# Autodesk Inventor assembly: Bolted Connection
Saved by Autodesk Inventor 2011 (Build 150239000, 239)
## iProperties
Created: 2020-12
Part Number: Bolted Connection
Document SubType Name: Assembly
Designer: PC
ClientObjectVersion: 1
Author: PC
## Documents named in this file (3)
- C:\Users\PC\Documents\Inventor\workshop-crane-powered-by-drill\estructura-principal\Design Accelerator\Bolted Connection5.iam
- C:\Users\PC\Documents\Inventor\Content Center Files\R2011\en-US\DIN 931-1\DIN 931-1 - M14 x 75.ipt
- C:\Users\PC\Documents\Inventor\Content Center Files\R2011\en-US\DIN 555\DIN 555-5 - M14.ipt
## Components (2 placed, 2 different names)
1. DIN 931-1 - replaced by DIN EN 24014 M14 x 75:1
2. DIN 555 - replaced by DIN EN 24034 M14:1
